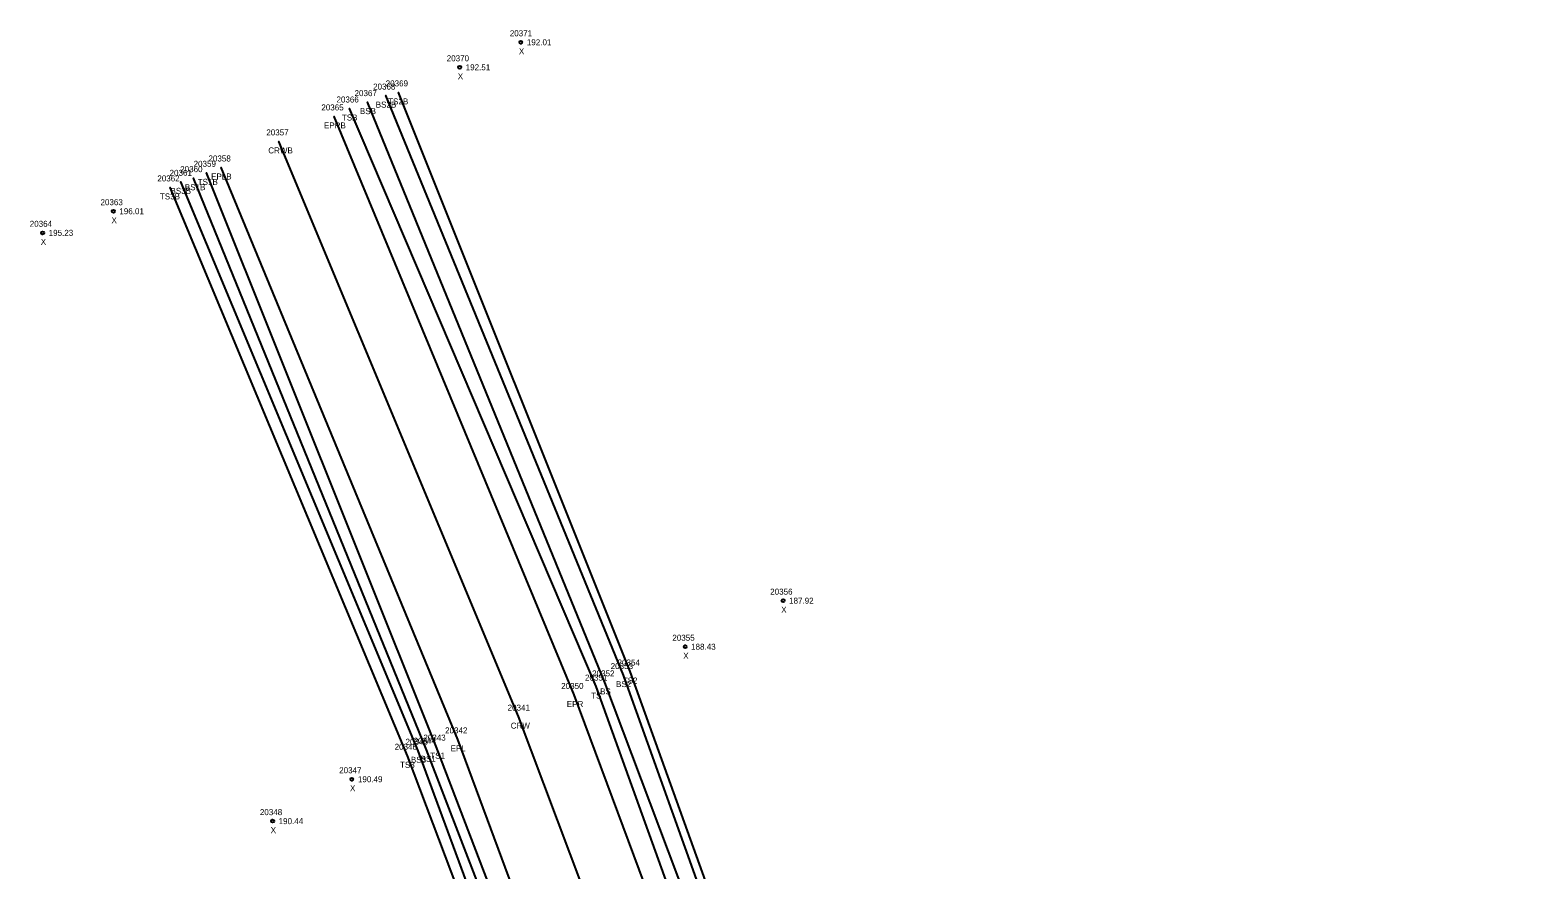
# Model space of a CAD drawing. Extents: x 2077883 to 2078272, y 787819 to 788945.
# Drawn here: x 2077883.5 to 2078134.4, y 788805.4 to 788945.2 of the extents above; entities that cross this region are included whole.
import ezdxf

# ---------------------------------------------------------------- set-up
doc = ezdxf.new("R2010")
doc.units = 0
for name, color, linetype in [('RD_DTM_BkLn1', 7, 'Continuous'), ('RD_DTM_BkLn2', 7, 'Continuous'), ('RD_EX_Road', 7, 'Continuous'), ('RD_EX_Road_txCode', 7, 'Continuous'), ('RD_Sketch8', 7, 'Continuous'), ('RD_SMD_Locator', 7, 'Continuous'), ('RD_SMD_Misc', 7, 'Continuous')]:
    doc.layers.add(name, color=color, linetype=linetype)

msp = doc.modelspace()

# ---------------------------------------------------------------- linework, layer by layer
at = {"layer": 'RD_DTM_BkLn1'}
msp.add_lwpolyline([(2078089.54, 788425.19), (2078086.71, 788437.21), (2078062.2, 788536.79), (2078033.97, 788636.37), (2078001.1, 788734.32), (2077964.77, 788830.93), (2077924.88, 788926.7)], dxfattribs=at)
at = {"layer": 'RD_DTM_BkLn2'}
for points in [[(2078133.54, 788471.13), (2078119.08, 788459.82), (2078109.91, 788458.97), (2078096.37, 788486), (2078083.98, 788526.2), (2078079.55, 788541.15), (2078062.23, 788600.27), (2078049.45, 788641.41), (2078015.58, 788739.83), (2077979.12, 788836.63), (2077939.6, 788933.24)], [(2078132.44, 788472.19), (2078118.34, 788466.81), (2078100.1, 788488.15), (2078085.17, 788526.48), (2078080.48, 788541.38), (2078063.7, 788600.7), (2078051.16, 788642.09), (2078017.07, 788740.46), (2077982.21, 788837.85), (2077942.69, 788934.33)], [(2078130.39, 788474.32), (2078119.21, 788468.58), (2078104.21, 788490.29), (2078085.93, 788526.63), (2078081.69, 788541.53), (2078065.4, 788601.95), (2078053.34, 788642.42), (2078018.45, 788740.81), (2077983.36, 788838.44), (2077944.78, 788934.86)], [(2078134.43, 788470.29), (2078120, 788457.99), (2078107.89, 788457.91), (2078093.72, 788484.84), (2078082.52, 788526.41), (2078077.77, 788540.75), (2078060.01, 788599.41), (2078046.63, 788640.05), (2078012.72, 788738.62), (2077977.66, 788835.93), (2077936.62, 788932.18)], [(2077999.51, 788689.45), (2077999.26, 788691.54), (2077986.65, 788728.72), (2077949.41, 788825.41), (2077910.63, 788920.58)], [(2078000.92, 788689.53), (2077988.11, 788729.08), (2077951.02, 788825.94), (2077912.79, 788921.47)], [(2078000.92, 788689.53), (2077998.64, 788688.34), (2077996.8, 788688.7), (2077982.94, 788727.21), (2077946.28, 788824.41), (2077906.77, 788919.04)], [(2077999.51, 788689.45), (2077997.32, 788690.77), (2077984.12, 788727.55), (2077948.07, 788825.25), (2077908.52, 788919.97)]]:
    msp.add_lwpolyline(points, dxfattribs=at)
at = {"layer": 'RD_EX_Road'}
for points in [[(2078107.13, 788420.86), (2078105.11, 788427.29), (2078111.84, 788429.2), (2078117.69, 788434.7), (2078115.66, 788443.13), (2078106.49, 788447.64), (2078097.77, 788449.71), (2078094.97, 788456.34), (2078072.64, 788539.43), (2078043.77, 788639.22), (2078010.2, 788737.35), (2077974.01, 788834.54), (2077934.07, 788930.86)], [(2078107.13, 788420.86), (2078092.81, 788417.62), (2078089.54, 788425.19), (2078083.84, 788425.84), (2078081.3, 788430.73), (2078074.53, 788432.67), (2078073.43, 788440.66), (2078071.07, 788452.5), (2078051.67, 788533.56), (2078023.01, 788633.14), (2078012.91, 788665.11), (2078004.86, 788689.7), (2077990.53, 788730.26), (2077954.65, 788827.14), (2077915.26, 788922.36)]]:
    msp.add_lwpolyline(points, dxfattribs=at)
at = {"layer": 'RD_SMD_Locator'}
for centre, radius in [((2077965.14, 788943.21), 0.25), ((2077954.96, 788939.04), 0.25), ((2077939.6, 788933.24), 0.001), ((2077942.69, 788934.33), 0.001), ((2077944.78, 788934.86), 0.001), ((2077934.07, 788930.86), 0.001), ((2077936.62, 788932.18), 0.001), ((2077924.88, 788926.7), 0.001), ((2077910.63, 788920.58), 0.001), ((2077912.79, 788921.47), 0.001), ((2077915.26, 788922.36), 0.001), ((2077906.77, 788919.04), 0.001), ((2077908.52, 788919.97), 0.001), ((2077897.31, 788915.08), 0.25), ((2077885.54, 788911.48), 0.25), ((2078008.79, 788850.24), 0.25), ((2077992.48, 788842.57), 0.25), ((2077982.21, 788837.85), 0.001), ((2077983.36, 788838.44), 0.001), ((2077977.66, 788835.93), 0.001), ((2077979.12, 788836.63), 0.001), ((2077974.01, 788834.54), 0.001), ((2077964.77, 788830.93), 0.001), ((2077948.07, 788825.25), 0.001), ((2077949.41, 788825.41), 0.001), ((2077951.02, 788825.94), 0.001), ((2077954.65, 788827.14), 0.001), ((2077946.28, 788824.41), 0.001), ((2077937.02, 788820.51), 0.25), ((2077923.82, 788813.53), 0.25)]:
    msp.add_circle(centre, radius, dxfattribs=at)

# ---------------------------------------------------------------- texts
at = {"layer": 'RD_EX_Road_txCode'}
for s, p in [('20365', (2077931.93, 788931.86)), ('EPRB', (2077932.37, 788928.86)), ('20358', (2077913.14, 788923.36)), ('EPLB', (2077913.58, 788920.36)), ('20350', (2077971.86, 788835.54)), ('EPR', (2077972.79, 788832.54)), ('20342', (2077952.53, 788828.14)), ('EPL', (2077953.44, 788825.14))]:
    msp.add_text(s, height=1, dxfattribs=at).set_placement(p)
at = {"layer": 'RD_Sketch8'}
for s, p in [('20371', (2077963.3, 788944.21)), ('192.01', (2077966.14, 788942.71)), ('20370', (2077952.8, 788940.04)), ('X', (2077964.82, 788941.21)), ('X', (2077954.64, 788937.04)), ('192.51', (2077955.96, 788938.54)), ('20363', (2077895.17, 788916.08)), ('196.01', (2077898.31, 788914.58)), ('20364', (2077883.39, 788912.48)), ('X', (2077897, 788913.08)), ('X', (2077885.22, 788909.48)), ('195.23', (2077886.54, 788910.98)), ('20356', (2078006.65, 788851.24)), ('187.92', (2078009.79, 788849.74)), ('X', (2078008.48, 788848.24)), ('20355', (2077990.36, 788843.57)), ('188.43', (2077993.48, 788842.07)), ('X', (2077992.17, 788840.57)), ('20347', (2077934.9, 788821.51)), ('190.49', (2077938.02, 788820.01)), ('X', (2077936.7, 788818.51)), ('20348', (2077921.7, 788814.53)), ('X', (2077923.5, 788811.53)), ('190.44', (2077924.82, 788813.03))]:
    msp.add_text(s, height=1, dxfattribs=at).set_placement(p)
at = {"layer": 'RD_SMD_Misc'}
for s, p in [('20367', (2077937.46, 788934.24)), ('20368', (2077940.55, 788935.33)), ('20369', (2077942.64, 788935.86)), ('20366', (2077934.45, 788933.18)), ('BS2B', (2077940.99, 788932.33)), ('TS2B', (2077943.06, 788932.86)), ('TSB', (2077935.35, 788930.18)), ('BSB', (2077938.35, 788931.24)), ('20357', (2077922.77, 788927.7)), ('CRWB', (2077923.1, 788924.7)), ('20360', (2077908.44, 788921.58)), ('20359', (2077910.67, 788922.47)), ('20362', (2077904.63, 788920.04)), ('20361', (2077906.67, 788920.97)), ('TS1B', (2077911.35, 788919.47)), ('TS3B', (2077905.06, 788917.04)), ('BS3B', (2077906.82, 788917.97)), ('BS1B', (2077909.21, 788918.58)), ('20353', (2077980.09, 788838.85)), ('20354', (2077981.24, 788839.44)), ('20351', (2077975.82, 788836.93)), ('20352', (2077977.01, 788837.63)), ('TS2', (2077982.11, 788836.44)), ('TS', (2077976.86, 788833.93)), ('BS', (2077978.34, 788834.63)), ('BS2', (2077980.98, 788835.85)), ('20341', (2077962.94, 788831.93)), ('CRW', (2077963.46, 788828.93)), ('20345', (2077945.95, 788826.25)), ('20344', (2077947.29, 788826.41)), ('20343', (2077948.91, 788826.94)), ('20346', (2077944.13, 788825.41)), ('TS1', (2077950.06, 788823.94)), ('TS3', (2077945.03, 788822.41)), ('BS3', (2077946.84, 788823.25)), ('BS1', (2077948.46, 788823.41))]:
    msp.add_text(s, height=1, dxfattribs=at).set_placement(p)

doc.saveas('drawing.dxf')
